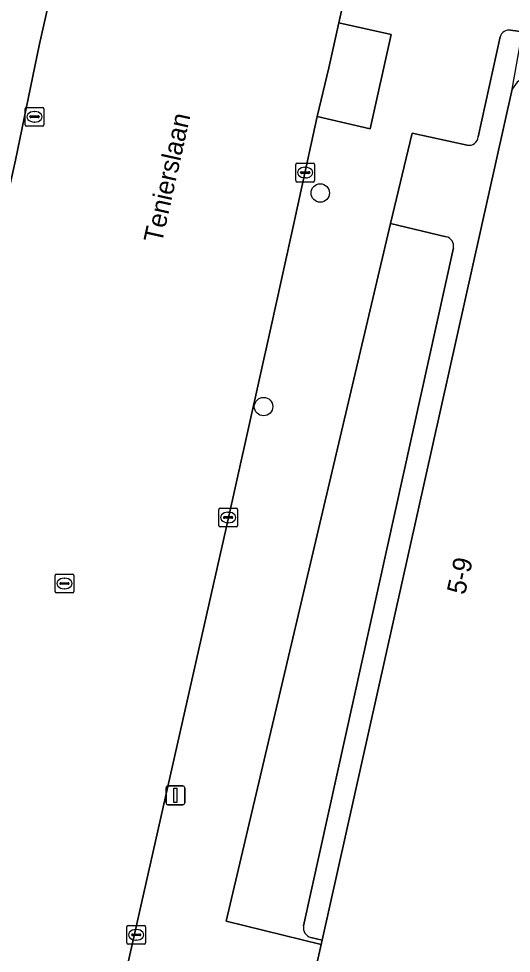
# Model space of a CAD drawing. Extents: x 162172 to 163187, y 382874 to 383685.
# Drawn here: x 162561.39 to 162587.5, y 383052.12 to 383101.71 of the extents above; entities that cross this region are included whole.
import ezdxf

# ---------------------------------------------------------------- set-up
doc = ezdxf.new("R2010")
doc.units = 0
for name, color, linetype in [('IMGEO_Boom', 7, 'Continuous'), ('IMGEO_Kolk', 7, 'Continuous'), ('IMGEO_Lichtmast', 7, 'Continuous'), ('IMGEO_Openbare_ruimte_label', 7, 'Continuous'), ('IMGEO_Pand', 7, 'Continuous'), ('IMGEO_Pand_nummerreeks', 7, 'Continuous'), ('IMGEO_Parkeervlak_open', 7, 'Continuous'), ('IMGEO_Rijbaan_lokaal_open', 7, 'Continuous'), ('IMGEO_Rioolput', 7, 'Continuous'), ('IMGEO_Voetpad_open', 7, 'Continuous')]:
    doc.layers.add(name, color=color, linetype=linetype)

msp = doc.modelspace()

# ---------------------------------------------------------------- linework, layer by layer
at = {"layer": 'IMGEO_Boom'}
for centre in [(162577.37, 383092.462), (162574.364, 383081.127)]:
    msp.add_circle(centre, 0.489, dxfattribs=at)
at = {"layer": 'IMGEO_Kolk'}
for p, q in [((162561.723, 383096.081), (162561.723, 383096.933)), ((162561.798, 383097.007), (162562.65, 383097.007)), ((162562.724, 383096.933), (162562.724, 383096.081)), ((162561.982, 383096.501), (162561.982, 383096.513)), ((162562.42, 383096.464), (162562.022, 383096.464)), ((162562.025, 383096.55), (162562.423, 383096.55)), ((162562.211, 383096.787), (162562.236, 383096.787)), ((162562.466, 383096.513), (162562.466, 383096.501)), ((162562.65, 383096.007), (162561.798, 383096.007)), ((162562.234, 383096.227), (162562.209, 383096.227)), ((162576.073, 383093.12), (162576.073, 383093.972)), ((162576.148, 383094.046), (162577, 383094.046)), ((162577.074, 383093.972), (162577.074, 383093.12)), ((162576.332, 383093.54), (162576.332, 383093.552)), ((162576.77, 383093.503), (162576.372, 383093.503)), ((162576.375, 383093.589), (162576.773, 383093.589)), ((162576.561, 383093.826), (162576.586, 383093.826)), ((162576.816, 383093.552), (162576.816, 383093.54)), ((162577, 383093.046), (162576.148, 383093.046)), ((162576.584, 383093.266), (162576.559, 383093.266)), ((162571.988, 383074.821), (162571.988, 383075.673)), ((162572.063, 383075.747), (162572.915, 383075.747)), ((162572.476, 383075.527), (162572.501, 383075.527)), ((162572.989, 383075.673), (162572.989, 383074.821)), ((162572.247, 383075.241), (162572.247, 383075.253)), ((162572.685, 383075.204), (162572.287, 383075.204)), ((162572.29, 383075.29), (162572.688, 383075.29)), ((162572.731, 383075.253), (162572.731, 383075.241)), ((162572.915, 383074.747), (162572.063, 383074.747)), ((162572.499, 383074.967), (162572.474, 383074.967)), ((162567.112, 383052.674), (162567.112, 383053.526)), ((162567.187, 383053.6), (162568.039, 383053.6)), ((162567.6, 383053.38), (162567.625, 383053.38)), ((162568.113, 383053.526), (162568.113, 383052.674)), ((162567.371, 383053.094), (162567.371, 383053.106)), ((162567.809, 383053.057), (162567.411, 383053.057)), ((162567.414, 383053.143), (162567.812, 383053.143)), ((162567.623, 383052.82), (162567.598, 383052.82)), ((162567.855, 383053.106), (162567.855, 383053.094)), ((162568.039, 383052.6), (162567.187, 383052.6))]:
    msp.add_line(p, q, dxfattribs=at)
for points in [[(162561.723, 383096.081), (162561.723, 383096.933)], [(162561.798, 383097.007), (162562.65, 383097.007)], [(162562.724, 383096.933), (162562.724, 383096.081)], [(162562.65, 383096.007), (162561.798, 383096.007)], [(162576.073, 383093.12), (162576.073, 383093.972)], [(162576.148, 383094.046), (162577, 383094.046)], [(162577.074, 383093.972), (162577.074, 383093.12)], [(162577, 383093.046), (162576.148, 383093.046)], [(162571.988, 383074.821), (162571.988, 383075.673)], [(162572.063, 383075.747), (162572.915, 383075.747)], [(162572.989, 383075.673), (162572.989, 383074.821)], [(162572.915, 383074.747), (162572.063, 383074.747)], [(162567.112, 383052.674), (162567.112, 383053.526)], [(162567.187, 383053.6), (162568.039, 383053.6)], [(162568.113, 383053.526), (162568.113, 383052.674)], [(162568.039, 383052.6), (162567.187, 383052.6)]]:
    msp.add_lwpolyline(points, dxfattribs=at)
for centre, radius, start, end in [((162561.8, 383096.931), 0.0765, 91.552, 178.448), ((162561.8, 383096.931), 0.0765, 91.552, 178.448), ((162562.648, 383096.931), 0.0765, 1.552, 88.448), ((162562.648, 383096.931), 0.0765, 1.552, 88.448), ((162562.022, 383096.51), 0.0403, 85.8775, 175.7526), ((162562.019, 383096.5), 0.0366, 178.938, 274.7102), ((162562.423, 383096.507), 0.043, 264.8664, 352.4533), ((162562.427, 383096.512), 0.0386, 1.7309, 96.639), ((162561.8, 383096.083), 0.0765, 181.552, 268.448), ((162561.8, 383096.083), 0.0765, 181.552, 268.448), ((162562.648, 383096.083), 0.0765, 271.552, 358.448), ((162562.648, 383096.083), 0.0765, 271.552, 358.448), ((162576.15, 383093.97), 0.0765, 91.552, 178.448), ((162576.15, 383093.97), 0.0765, 91.552, 178.448), ((162576.998, 383093.97), 0.0765, 1.552, 88.448), ((162576.998, 383093.97), 0.0765, 1.552, 88.448), ((162576.372, 383093.549), 0.0403, 85.8775, 175.7526), ((162576.369, 383093.539), 0.0366, 178.938, 274.7102), ((162576.773, 383093.546), 0.043, 264.8664, 352.4533), ((162576.777, 383093.551), 0.0386, 1.7309, 96.639), ((162576.15, 383093.122), 0.0765, 181.552, 268.448), ((162576.15, 383093.122), 0.0765, 181.552, 268.448), ((162576.998, 383093.122), 0.0765, 271.552, 358.448), ((162576.998, 383093.122), 0.0765, 271.552, 358.448), ((162572.065, 383075.671), 0.0765, 91.552, 178.448), ((162572.065, 383075.671), 0.0765, 91.552, 178.448), ((162572.913, 383075.671), 0.0765, 1.552, 88.448), ((162572.913, 383075.671), 0.0765, 1.552, 88.448), ((162572.287, 383075.25), 0.0403, 85.8775, 175.7526), ((162572.284, 383075.24), 0.0366, 178.938, 274.7102), ((162572.688, 383075.247), 0.043, 264.8664, 352.4533), ((162572.692, 383075.252), 0.0386, 1.7309, 96.639), ((162572.065, 383074.823), 0.0765, 181.552, 268.448), ((162572.065, 383074.823), 0.0765, 181.552, 268.448), ((162572.913, 383074.823), 0.0765, 271.552, 358.448), ((162572.913, 383074.823), 0.0765, 271.552, 358.448), ((162567.189, 383053.524), 0.0765, 91.552, 178.448), ((162567.189, 383053.524), 0.0765, 91.552, 178.448), ((162568.037, 383053.524), 0.0765, 1.552, 88.448), ((162568.037, 383053.524), 0.0765, 1.552, 88.448), ((162567.411, 383053.103), 0.0403, 85.8775, 175.7526), ((162567.408, 383053.093), 0.0366, 178.938, 274.7102), ((162567.812, 383053.1), 0.043, 264.8664, 352.4533), ((162567.816, 383053.105), 0.0386, 1.7309, 96.639), ((162567.189, 383052.676), 0.0765, 181.552, 268.448), ((162567.189, 383052.676), 0.0765, 181.552, 268.448), ((162568.037, 383052.676), 0.0765, 271.552, 358.448), ((162568.037, 383052.676), 0.0765, 271.552, 358.448)]:
    msp.add_arc(centre, radius, start, end, dxfattribs=at)
for centre, major_axis, ratio, start_param, end_param in [((162562.21, 383096.507), (-0.387, 0.002), 0.722429, 4.712389, 7.853982), ((162562.235, 383096.507), (-0.39, 0.002), 0.717154, 1.570796, 4.712389), ((162576.56, 383093.546), (-0.387, 0.002), 0.722429, 4.712389, 7.853982), ((162576.585, 383093.546), (-0.39, 0.002), 0.717154, 1.570796, 4.712389), ((162572.475, 383075.247), (-0.387, 0.002), 0.722429, 4.712389, 7.853982), ((162572.5, 383075.247), (-0.39, 0.002), 0.717154, 1.570796, 4.712389), ((162567.599, 383053.1), (-0.387, 0.002), 0.722429, 4.712389, 7.853982), ((162567.624, 383053.1), (-0.39, 0.002), 0.717154, 1.570796, 4.712389)]:
    msp.add_ellipse(centre, major_axis=major_axis, ratio=ratio, start_param=start_param, end_param=end_param, dxfattribs=at)
at = {"layer": 'IMGEO_Lichtmast'}
for p, q in [((162569.196, 383060.102), (162569.196, 383060.902)), ((162569.196, 383060.902), (162569.196, 383060.102)), ((162569.296, 383061.002), (162570.086, 383061.002)), ((162570.086, 383061.002), (162569.296, 383061.002)), ((162570.186, 383060.902), (162570.186, 383060.102)), ((162570.186, 383060.102), (162570.186, 383060.902)), ((162570.086, 383060.002), (162569.296, 383060.002)), ((162569.296, 383060.002), (162570.086, 383060.002))]:
    msp.add_line(p, q, dxfattribs=at)
msp.add_lwpolyline([(162569.616, 383060.877), (162569.766, 383060.877), (162569.766, 383060.127), (162569.616, 383060.127), (162569.616, 383060.877)], dxfattribs=at)
for centre, start, end in [((162569.296, 383060.902), 90, 180), ((162569.296, 383060.902), 90, 180), ((162570.086, 383060.902), 0, 90), ((162570.086, 383060.902), 360, 90), ((162569.296, 383060.102), 180, 270), ((162569.296, 383060.102), 180, 270), ((162570.086, 383060.102), 270, 0), ((162570.086, 383060.102), 270, 0)]:
    msp.add_arc(centre, 0.1, start, end, dxfattribs=at)
at = {"layer": 'IMGEO_Pand'}
msp.add_lwpolyline([(162600.513, 383082.384), (162602.842, 383092.735), (162603.52, 383095.749), (162589.13, 383098.96), (162588.453, 383098.802), (162587.817, 383098.35), (162587.542, 383097.969), (162577.465, 383052.811), (162577.413, 383052.58), (162576.647, 383049.119), (162576.596, 383048.889), (162592.267, 383045.42)], close=True, dxfattribs=at)
at = {"layer": 'IMGEO_Parkeervlak_open'}
msp.add_lwpolyline([(162578.357, 383101.491), (162577.818, 383099.107), (162577.214, 383096.517), (162580.025, 383095.859), (162581.137, 383100.866)], close=True, dxfattribs=at)
for points in [[(162584.04, 383090.14), (162581.102, 383090.845), (162572.38, 383053.821), (162577.413, 383052.58), (162577.465, 383052.811), (162576.878, 383052.958)], [(162576.484, 383053.576), (162584.427, 383089.547)]]:
    msp.add_lwpolyline(points, dxfattribs=at)
for centre, radius, start, end in [((162583.951, 383089.659), 0.489, 346.6977, 79.5604), ((162577.008, 383053.476), 0.534, 169.1688, 255.8695)]:
    msp.add_arc(centre, radius, start, end, dxfattribs=at)
at = {"layer": 'IMGEO_Rijbaan_lokaal_open'}
for points in [[(162579.472, 383177.4), (162579.006, 383174.463), (162576.34, 383162.62), (162575.738, 383159.962), (162573.627, 383149.824), (162571.847, 383141.703), (162568.093, 383125.214), (162565.752, 383114.895), (162564.59, 383109.703), (162562.464, 383100.284), (162561.209, 383094.198), (162559.406, 383086.19), (162556.009, 383071.037)], [(162565.066, 383042.173), (162565.695, 383045.02), (162565.915, 383046.006), (162568.264, 383056.423), (162571.587, 383071.156), (162572.387, 383074.686), (162574.753, 383085.311), (162575.844, 383090.279), (162577.214, 383096.517), (162577.818, 383099.107), (162578.357, 383101.491), (162579.85, 383108.231), (162580.892, 383112.905), (162584.135, 383127.261)]]:
    msp.add_lwpolyline(points, dxfattribs=at)
at = {"layer": 'IMGEO_Rioolput'}
for p, q in [((162563.31, 383071.317), (162563.31, 383072.169)), ((162563.385, 383072.243), (162564.237, 383072.243)), ((162563.798, 383072.023), (162563.823, 383072.023)), ((162564.311, 383072.169), (162564.311, 383071.317)), ((162563.569, 383071.737), (162563.569, 383071.749)), ((162564.007, 383071.7), (162563.609, 383071.7)), ((162563.612, 383071.786), (162564.01, 383071.786)), ((162564.053, 383071.749), (162564.053, 383071.737)), ((162564.237, 383071.243), (162563.385, 383071.243)), ((162563.821, 383071.463), (162563.796, 383071.463))]:
    msp.add_line(p, q, dxfattribs=at)
for points in [[(162563.31, 383071.317), (162563.31, 383072.169)], [(162563.385, 383072.243), (162564.237, 383072.243)], [(162564.311, 383072.169), (162564.311, 383071.317)], [(162564.237, 383071.243), (162563.385, 383071.243)]]:
    msp.add_lwpolyline(points, dxfattribs=at)
for centre, radius, start, end in [((162563.387, 383072.167), 0.0765, 91.552, 178.448), ((162563.387, 383072.167), 0.0765, 91.552, 178.448), ((162564.235, 383072.167), 0.0765, 1.552, 88.448), ((162564.235, 383072.167), 0.0765, 1.552, 88.448), ((162563.609, 383071.746), 0.0403, 85.8775, 175.7526), ((162563.606, 383071.736), 0.0366, 178.938, 274.7102), ((162564.01, 383071.743), 0.043, 264.8664, 352.4533), ((162564.014, 383071.748), 0.0386, 1.7309, 96.639), ((162563.387, 383071.319), 0.0765, 181.552, 268.448), ((162563.387, 383071.319), 0.0765, 181.552, 268.448), ((162564.235, 383071.319), 0.0765, 271.552, 358.448), ((162564.235, 383071.319), 0.0765, 271.552, 358.448)]:
    msp.add_arc(centre, radius, start, end, dxfattribs=at)
for centre, major_axis, ratio, start_param, end_param in [((162563.797, 383071.743), (-0.387, 0.002), 0.722429, 4.712389, 7.853982), ((162563.822, 383071.743), (-0.39, 0.002), 0.717154, 1.570796, 4.712389)]:
    msp.add_ellipse(centre, major_axis=major_axis, ratio=ratio, start_param=start_param, end_param=end_param, dxfattribs=at)
at = {"layer": 'IMGEO_Voetpad_open'}
for points in [[(162556.009, 383071.037), (162559.406, 383086.19), (162561.209, 383094.198), (162562.464, 383100.284), (162564.59, 383109.703), (162565.752, 383114.895), (162568.093, 383125.214), (162571.847, 383141.703), (162573.627, 383149.824)], [(162587.454, 383101.104), (162588.111, 383101.011), (162591.717, 383117.299), (162586.656, 383118.417), (162585.234, 383111.98), (162584.187, 383107.254), (162579.85, 383108.231), (162578.357, 383101.491), (162581.137, 383100.866), (162580.025, 383095.859), (162577.214, 383096.517), (162575.844, 383090.279), (162574.753, 383085.311), (162572.387, 383074.686), (162571.587, 383071.156), (162568.264, 383056.423), (162565.915, 383046.006), (162565.695, 383045.02), (162565.066, 383042.173)], [(162576.878, 383052.958), (162577.465, 383052.811), (162587.542, 383097.969), (162588.005, 383100.532), (162588.111, 383101.011), (162587.454, 383101.104)], [(162585.748, 383095.437), (162586.906, 383100.752)], [(162586.906, 383100.752), (162585.748, 383095.437)], [(162581.102, 383090.845), (162582.241, 383095.642), (162585.159, 383095)], [(162585.159, 383095), (162582.241, 383095.642), (162581.102, 383090.845), (162584.04, 383090.14)], [(162568.518, 383024.457), (162570.901, 383023.915), (162571.622, 383027.04), (162570.641, 383027.19), (162566.728, 383028.095), (162567.134, 383029.908), (162567.351, 383031.021), (162567.494, 383031.611), (162568.726, 383037.513), (162568.845, 383038.064), (162569.141, 383039.246), (162569.447, 383040.649), (162569.639, 383041.512), (162569.955, 383042.985), (162571.516, 383050.25), (162576.647, 383049.119), (162577.413, 383052.58), (162572.38, 383053.821), (162581.102, 383090.845)], [(162584.427, 383089.547), (162576.484, 383053.576)]]:
    msp.add_lwpolyline(points, dxfattribs=at)
for centre, radius, start, end in [((162587.384, 383100.61), 0.499, 81.9638, 163.4644), ((162587.384, 383100.61), 0.499, 81.9638, 163.4644), ((162585.244, 383095.501), 0.508, 260.3499, 352.7962), ((162585.244, 383095.501), 0.508, 260.3499, 352.7962), ((162583.951, 383089.659), 0.489, 346.6977, 79.5604), ((162577.008, 383053.476), 0.534, 169.1688, 255.8695)]:
    msp.add_arc(centre, radius, start, end, dxfattribs=at)

# ---------------------------------------------------------------- texts
at = {"layer": 'IMGEO_Openbare_ruimte_label'}
msp.add_text('Tenierslaan', height=1, rotation=77.409, dxfattribs=at).set_placement((162568.971, 383089.759))
at = {"layer": 'IMGEO_Pand_nummerreeks'}
msp.add_text('5-9', height=1, rotation=77.318, dxfattribs=at).set_placement((162585.041, 383071.106))

doc.saveas('drawing.dxf')
